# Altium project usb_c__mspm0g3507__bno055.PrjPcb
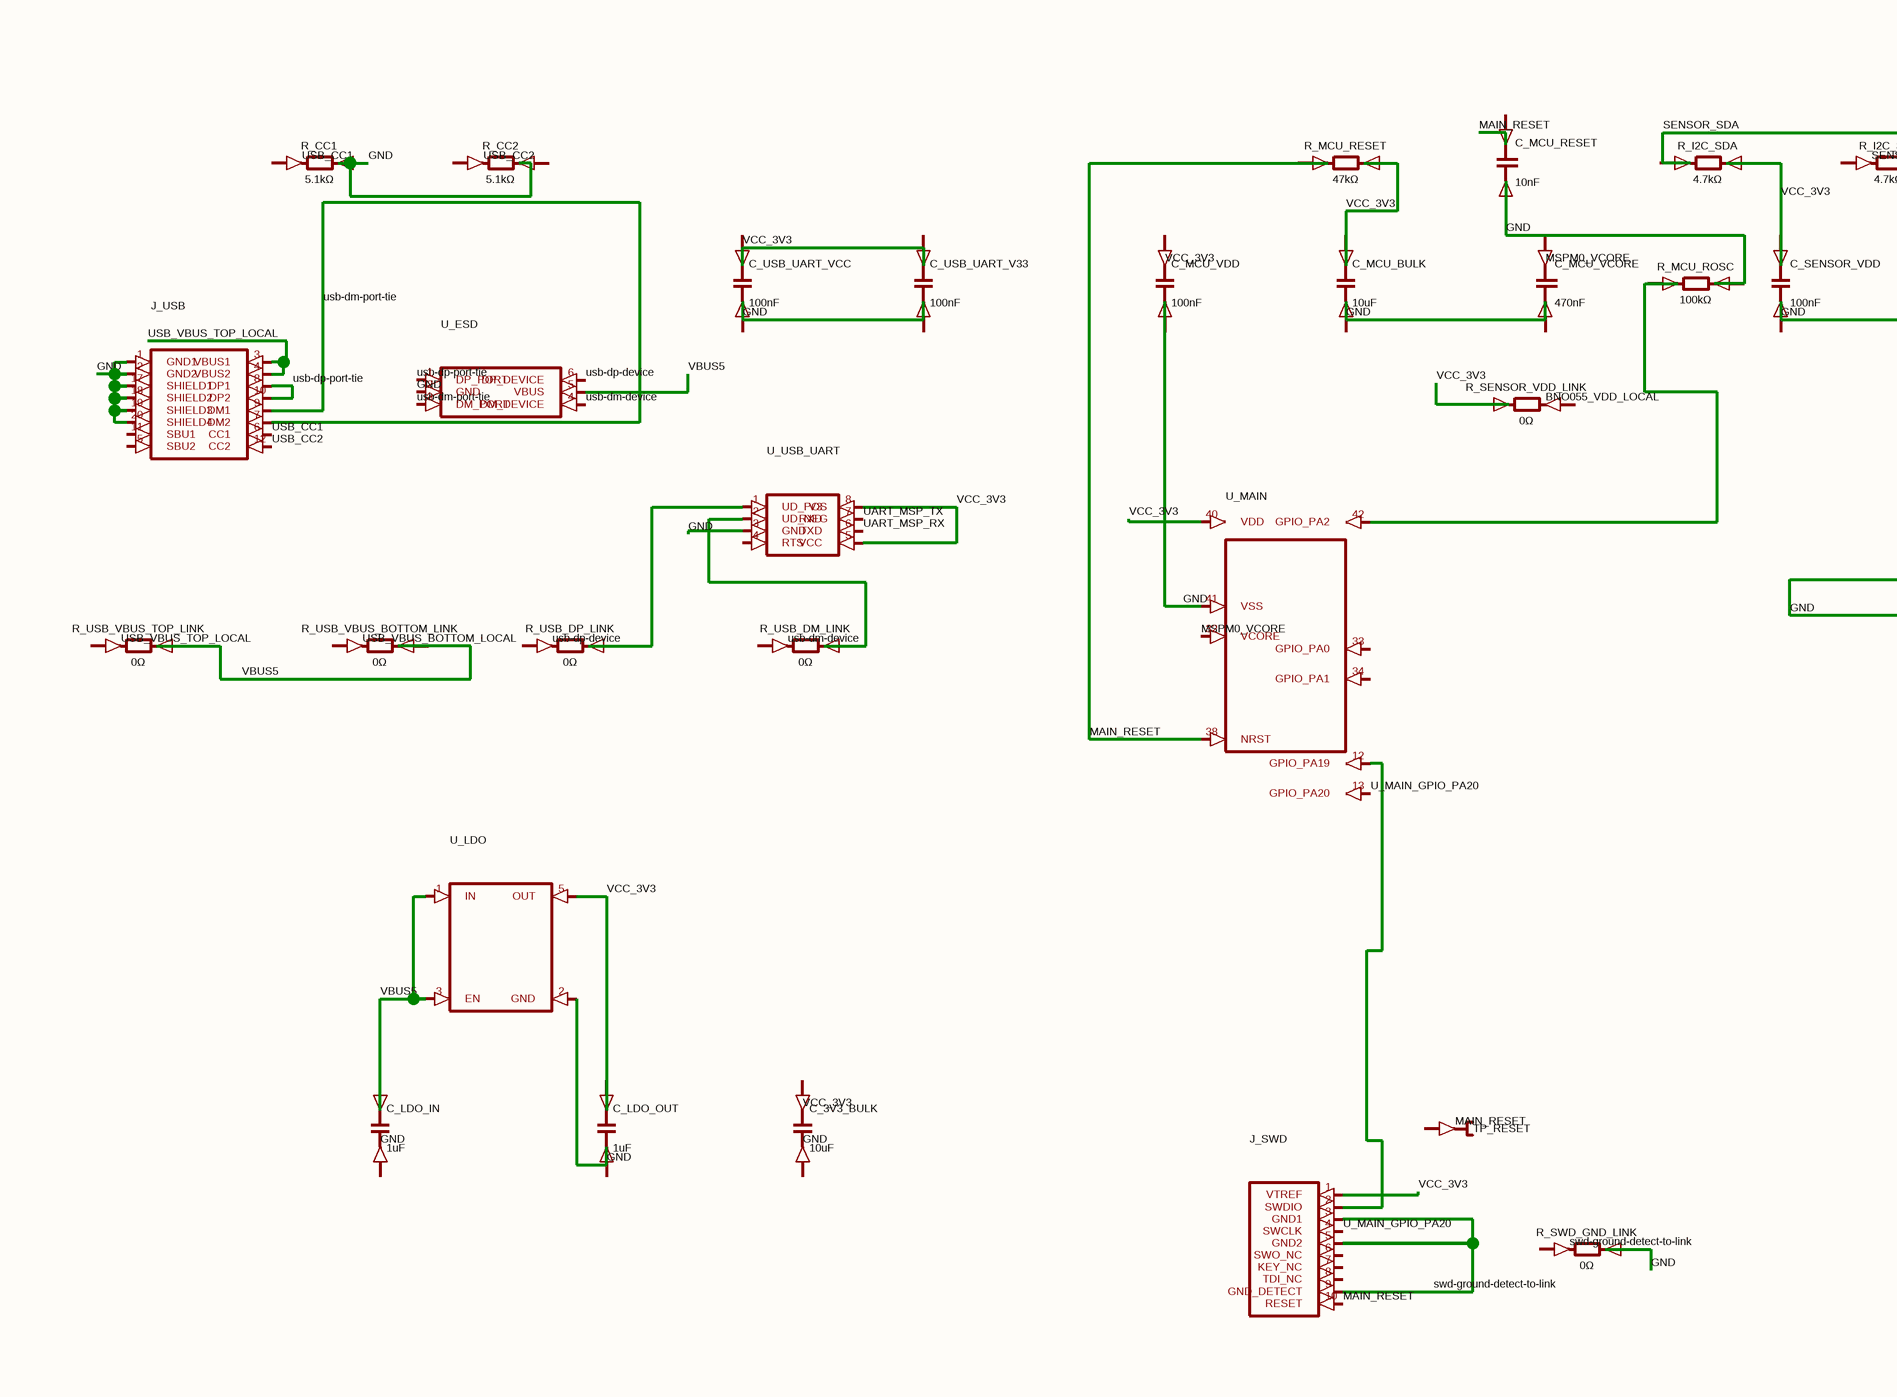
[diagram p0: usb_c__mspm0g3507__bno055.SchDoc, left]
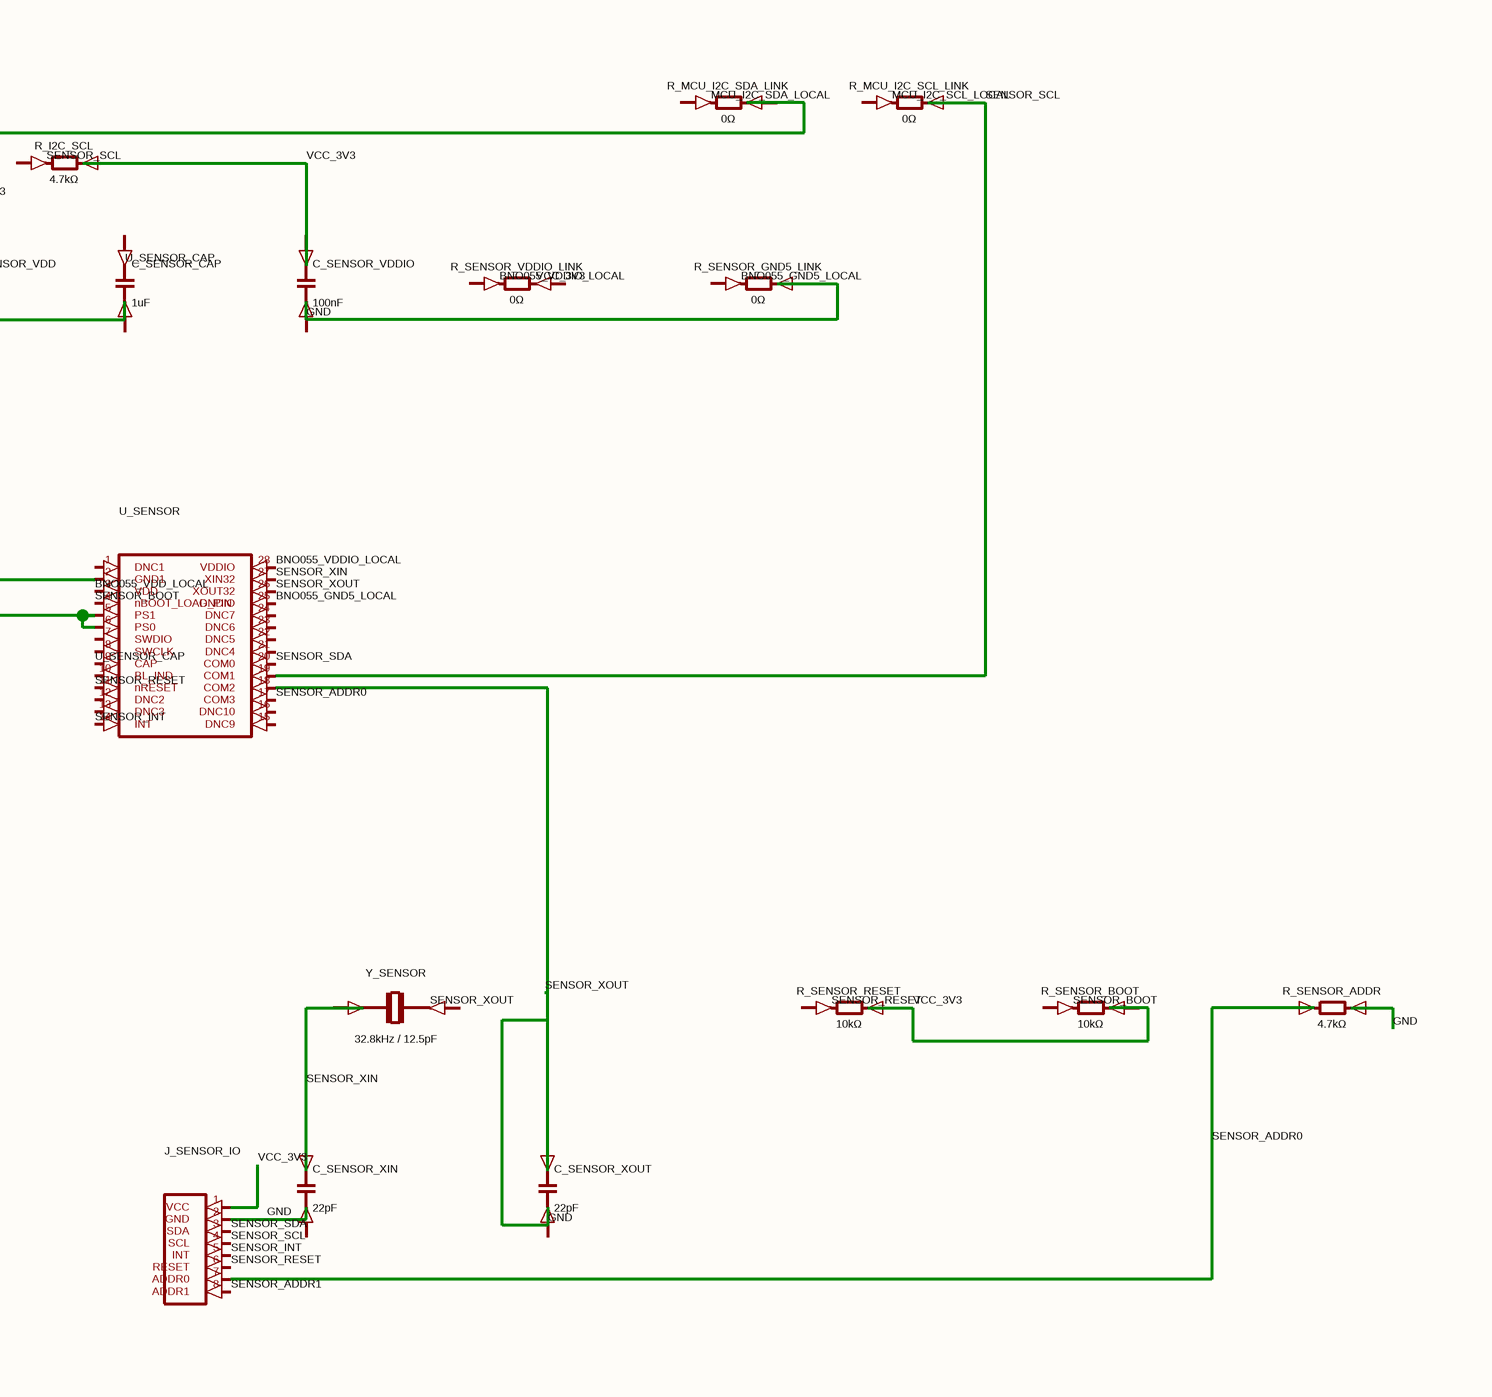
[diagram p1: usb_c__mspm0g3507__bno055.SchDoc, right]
1 sheet, 43 parts. Net scope: global (net labels, ports and power ports of the same name join across sheets).
Board file: usb_c__mspm0g3507__bno055.PcbDoc

## Sheet usb_c__mspm0g3507__bno055.SchDoc
size 317 x 151 mm

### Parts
C_3V3_BULK  10uF
C_LDO_IN  1uF
C_LDO_OUT  1uF
C_MCU_BULK  10uF
C_MCU_RESET  10nF
C_MCU_VCORE  470nF
C_MCU_VDD  100nF
C_SENSOR_CAP  1uF
C_SENSOR_VDD  100nF
C_SENSOR_VDDIO  100nF
C_SENSOR_XIN  22pF
C_SENSOR_XOUT  22pF
C_USB_UART_V33  100nF
C_USB_UART_VCC  100nF
J_SENSOR_IO  (no value)
J_SWD  (no value)
J_USB  (no value)
R_CC1  5.1kΩ
R_CC2  5.1kΩ
R_I2C_SCL  4.7kΩ
R_I2C_SDA  4.7kΩ
R_MCU_I2C_SCL_LINK  0Ω
R_MCU_I2C_SDA_LINK  0Ω
R_MCU_RESET  47kΩ
R_MCU_ROSC  100kΩ
R_SENSOR_ADDR  4.7kΩ
R_SENSOR_BOOT  10kΩ
R_SENSOR_GND5_LINK  0Ω
R_SENSOR_RESET  10kΩ
R_SENSOR_VDD_LINK  0Ω
R_SENSOR_VDDIO_LINK  0Ω
R_SWD_GND_LINK  0Ω
R_USB_DM_LINK  0Ω
R_USB_DP_LINK  0Ω
R_USB_VBUS_BOTTOM_LINK  0Ω
R_USB_VBUS_TOP_LINK  0Ω
TP_RESET  (no value)
U_ESD  (no value)
U_LDO  (no value)
U_MAIN  (no value)
U_SENSOR  (no value)
U_USB_UART  (no value)
Y_SENSOR  32.8kHz / 12.5pF

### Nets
BNO055_GND5_LOCAL: U_SENSOR.25(GNDIO)
BNO055_VDD_LOCAL: U_SENSOR.3(VDD)
BNO055_VDDIO_LOCAL: U_SENSOR.28(VDDIO)
GND: C_MCU_RESET.2(cathode) C_MCU_VCORE.1(anode) C_MCU_VDD.2(cathode) C_SENSOR_XOUT.1(anode) J_SENSOR_IO.2(GND) J_USB.1(GND1) J_USB.2(GND2) J_USB.17(SHIELD1) J_USB.18(SHIELD2) J_USB.19(SHIELD3) J_USB.20(SHIELD4) R_CC1.2(cathode) R_MCU_ROSC.2(cathode) R_SENSOR_ADDR.2(cathode) R_SENSOR_GND5_LINK.2(cathode) R_SWD_GND_LINK.2(cathode) R_USB_DM_LINK.2(cathode) U_ESD.2(GND) U_LDO.2(GND) U_MAIN.41(VSS) U_SENSOR.2(GND1) U_SENSOR.5(PS1) U_SENSOR.6(PS0) U_SENSOR.18(COM2) U_SENSOR.26(XOUT32) U_USB_UART.2(UD_NEG) U_USB_UART.3(GND)  [also labelled SENSOR_XOUT]
MAIN_RESET: J_SWD.10(RESET) R_MCU_RESET.1(anode) U_MAIN.38(NRST)
MSPM0_VCORE: U_MAIN.32(VCORE)
SENSOR_ADDR0: J_SENSOR_IO.7(ADDR0) R_SENSOR_ADDR.1(anode) U_SENSOR.17(COM3)
SENSOR_ADDR1: J_SENSOR_IO.8(ADDR1)
SENSOR_BOOT: U_SENSOR.4(nBOOT_LOAD_PIN)
SENSOR_INT: J_SENSOR_IO.5(INT) U_SENSOR.14(INT)
SENSOR_RESET: J_SENSOR_IO.6(RESET) U_SENSOR.11(nRESET)
SENSOR_SCL: J_SENSOR_IO.4(SCL) R_MCU_I2C_SCL_LINK.2(cathode) U_SENSOR.19(COM1)
SENSOR_SDA: J_SENSOR_IO.3(SDA) R_MCU_I2C_SDA_LINK.2(cathode) U_SENSOR.20(COM0)
SENSOR_XIN: C_SENSOR_XIN.1(anode) U_SENSOR.27(XIN32) Y_SENSOR.1(pos)
swd-ground-detect-to-link: J_SWD.3(GND1) J_SWD.5(GND2) J_SWD.9(GND_DETECT)
U_MAIN_GPIO_PA20: J_SWD.4(SWCLK) U_MAIN.13(GPIO_PA20)
U_SENSOR_CAP: U_SENSOR.9(CAP)
UART_MSP_RX: U_USB_UART.6(TXD)
UART_MSP_TX: U_USB_UART.7(RXD)
usb-dm-device: U_ESD.4(DM_DEVICE)
usb-dm-port-tie: C_LDO_IN.1(anode) J_USB.7(DM2) J_USB.9(DM1) R_USB_VBUS_BOTTOM_LINK.2(cathode) R_USB_VBUS_TOP_LINK.2(cathode) U_ESD.3(DM_PORT) U_ESD.5(VBUS) U_LDO.1(IN) U_LDO.3(EN)  [also labelled VBUS5]
usb-dp-device: U_ESD.6(DP_DEVICE)
usb-dp-port-tie: J_USB.8(DP1) J_USB.10(DP2) U_ESD.1(DP_PORT)
USB_CC1: J_USB.6(CC1)
USB_CC2: J_USB.12(CC2)
USB_VBUS_TOP_LOCAL: J_USB.3(VBUS1) J_USB.4(VBUS2)
VCC_3V3: C_LDO_OUT.1(anode) C_MCU_BULK.1(anode) C_SENSOR_VDD.1(anode) C_SENSOR_VDDIO.1(anode) J_SENSOR_IO.1(VCC) J_SWD.1(VTREF) R_I2C_SCL.2(cathode) R_I2C_SDA.2(cathode) R_MCU_RESET.2(cathode) R_SENSOR_BOOT.2(cathode) R_SENSOR_RESET.2(cathode) R_SENSOR_VDD_LINK.1(anode) U_LDO.5(OUT) U_MAIN.40(VDD) U_USB_UART.5(VCC) U_USB_UART.8(V3)
NetJ_SWD_2: J_SWD.2(SWDIO) U_MAIN.12(GPIO_PA19)
NetR_MCU_ROSC_1: R_MCU_ROSC.1(anode) U_MAIN.42(GPIO_PA2)
NetR_USB_DP_LINK_2: R_USB_DP_LINK.2(cathode) U_USB_UART.1(UD_POS)

Not connected (* = marked no-connect by the designer): C_3V3_BULK 1(anode) 2(cathode); C_LDO_IN 2(cathode); C_LDO_OUT 2(cathode); C_MCU_BULK 2(cathode); C_MCU_RESET 1(anode); C_MCU_VCORE 2(cathode); C_MCU_VDD 1(anode); C_SENSOR_CAP 1(anode) 2(cathode); C_SENSOR_VDD 2(cathode); C_SENSOR_VDDIO 2(cathode); C_SENSOR_XIN 2(cathode); C_SENSOR_XOUT 2(cathode); C_USB_UART_V33 1(anode) 2(cathode); C_USB_UART_VCC 1(anode) 2(cathode); J_SWD 6(SWO_NC) 7(KEY_NC) 8(TDI_NC); J_USB 5(SBU2) 11(SBU1); R_CC1 1(anode); R_CC2 1(anode) 2(cathode); R_I2C_SCL 1(anode); R_I2C_SDA 1(anode); R_MCU_I2C_SCL_LINK 1(anode); R_MCU_I2C_SDA_LINK 1(anode); R_SENSOR_BOOT 1(anode); R_SENSOR_GND5_LINK 1(anode); R_SENSOR_RESET 1(anode); R_SENSOR_VDD_LINK 2(cathode); R_SENSOR_VDDIO_LINK 1(anode) 2(cathode); R_SWD_GND_LINK 1(anode); R_USB_DM_LINK 1(anode); R_USB_DP_LINK 1(anode); R_USB_VBUS_BOTTOM_LINK 1(anode); R_USB_VBUS_TOP_LINK 1(anode); TP_RESET 1(pin1); U_MAIN 33(GPIO_PA0) 34(GPIO_PA1); U_SENSOR 1(DNC1) 7(SWDIO) 8(SWCLK) 10(BL_IND) 12(DNC2) 13(DNC3) 15(DNC9) 16(DNC10) 21(DNC4) 22(DNC5) 23(DNC6) 24(DNC7); U_USB_UART 4(RTS); Y_SENSOR 2(neg)

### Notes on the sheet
- Labels drawn without touching a wire or pin: BNO055_GND5_LOCAL, BNO055_VDD_LOCAL, BNO055_VDDIO_LOCAL, GND, MAIN_RESET, MCU_I2C_SCL_LOCAL, MCU_I2C_SDA_LOCAL, MSPM0_VCORE, SENSOR_BOOT, SENSOR_RESET, SENSOR_SCL, SENSOR_XOUT, swd-ground-detect-to-link, U_SENSOR_CAP, usb-dm-device, usb-dp-device, USB_CC1, USB_CC2, USB_VBUS_BOTTOM_LOCAL, USB_VBUS_TOP_LOCAL, VCC_3V3

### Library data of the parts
C_3V3_BULK C_LDO_IN C_LDO_OUT C_MCU_BULK C_MCU_RESET C_MCU_VCORE C_MCU_VDD C_SENSOR_CAP C_SENSOR_VDD C_SENSOR_VDDIO C_SENSOR_XIN C_SENSOR_XOUT C_USB_UART_V33 C_USB_UART_VCC = capacitor_down
J_SENSOR_IO = J_SENSOR_IO
J_SWD = J_SWD
J_USB = J_USB
R_CC1 R_CC2 R_I2C_SCL R_I2C_SDA R_MCU_I2C_SCL_LINK R_MCU_I2C_SDA_LINK R_MCU_RESET R_MCU_ROSC R_SENSOR_ADDR R_SENSOR_BOOT R_SENSOR_GND5_LINK R_SENSOR_RESET R_SENSOR_VDD_LINK R_SENSOR_VDDIO_LINK R_SWD_GND_LINK R_USB_DM_LINK R_USB_DP_LINK R_USB_VBUS_BOTTOM_LINK R_USB_VBUS_TOP_LINK = boxresistor_right
TP_RESET = testpoint_right
U_ESD = U_ESD
U_LDO = U_LDO
U_MAIN = U_MAIN
U_SENSOR = U_SENSOR
U_USB_UART = U_USB_UART
Y_SENSOR = crystal_right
